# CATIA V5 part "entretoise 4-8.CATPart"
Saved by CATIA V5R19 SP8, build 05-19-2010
Part number: entretoise 4-8
Revision: ANY
Definition: UNKNOWN
Nomenclature: entretoise 4-8
Source: Unknown
Bounding box of the stored display mesh (mm): x -4 to 4, y -3.991 to 3.991, z 0 to 3
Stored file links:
  D:\Documents\1_Travail\1 - ac-limoges.fr\ac-limoges.fr\Emmanuel Maynard - STI2D_Turgot\2 -2I2D\2_SEQUENCE_Serrure_Biométrique\5-Spé_ITEC\Serrure_Bio_Eleve\entretoise 4-8.CATPart
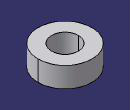
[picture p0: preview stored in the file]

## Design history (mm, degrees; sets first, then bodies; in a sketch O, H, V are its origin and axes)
Body1 "Extrusion1" (main body)
  Solid1: solid without history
